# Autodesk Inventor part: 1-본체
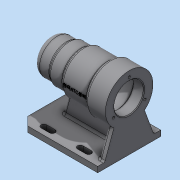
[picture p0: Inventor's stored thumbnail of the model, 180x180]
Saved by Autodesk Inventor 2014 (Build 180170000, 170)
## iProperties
Created: 2017-09
Part Number: 1-본체
Material: Generic
Document SubType Name: Modeling
Designer: user
Density: 1 g/cm^3
Appearance: Default
Author: user
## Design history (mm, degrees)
sketch "Sketch1"
  geometry: L1 (0, 0)-(25, 0); L2 (25, 0)-(25, 25); L3 (25, 25)-(0, 25); L4 (0, 25)-(0, 0); L5 (25, 0)-(45, 0); L6 (45, 0)-(45, 27); L7 (45, 27)-(25, 27); L8 (25, 27)-(25, 0); L9 (45, 0)-(84, 0); L10 (84, 0)-(84, 30); L11 (84, 30)-(45, 30); L12 (45, 30)-(45, 0); L13 (84, 0)-(112, 0); L14 (112, 0)-(112, 34); L15 (112, 34)-(84, 34); L16 (84, 34)-(84, 0)
  constraints: 32 end point, 8 parallel, 4 horizontal, 4 perpendicular
  dimensions: "d0" = 25 distance between parallel lines of L2 L4; "d1" = 45 distance between parallel lines of L6 L4; "d2" = 84 distance between parallel lines of L10 L4; "d3" = 112 distance between parallel lines of L14 L4; "d4" = 60 diameter of L11 L9; "d5" = 54 diameter of L7 L5; "d6" = 50 diameter of L3 L1; "d7" = 68 diameter of L15 L13
revolve "Revolution1" sketch "Sketch1" stored, may be unused: angle "d8" = 90 deg
workplane "Work Plane1"
sketch "Sketch2"
  geometry: L1 (0, -45)-(-112, -45); L2 (-112, -45)-(-112, 45); L3 (-112, 45)-(0, 45); L4 (0, 45)-(0, -45); L5 (-112, 34)-(-112, -34) reference; 3 further points
  constraints: 8 end point, 3 midpoint, 2 parallel, 1 coincident, 1 horizontal, 1 perpendicular
  dimensions: "d10" = 112 distance of L1.start L1.end; "d11" = 90 distance of L1.end L2.end
extrude "Extrusion1" join sketch "Sketch2" distance "d12" = 8; taper "d13" = 0 deg
sketch "Sketch3"
  geometry: L1 (0, 45)-(0, -45) reference; L2 (112, -45)-(112, 45) reference; L3 (22, 4)-(112, 4); L4 (112, 4)-(112, -4); L5 (112, -4)-(22, -4); L6 (22, -4)-(22, 4); 2 further points
  constraints: 8 end point, 2 midpoint, 2 parallel, 1 horizontal, 1 perpendicular, 1 point on line
  dimensions: "d14" = 22 distance between parallel lines of L6 L1; "d15" = 8 distance of L5.end L3.start
extrude "Extrusion2" join sketch "Sketch3" stored distance "d16" = 8; taper "d17" = 0 deg
feature "FaceDraft1" dims angle "d18" = 15 deg
sketch "Sketch4"
  geometry: L1 (90, 0)-(90, 8) reference; L2 (49, 8)-(90, 8) reference; L3 (41, 8)-(41, 36.236) reference; L4 (0, 8)-(41, 8) reference; L5 (0, 0)-(0, 8) reference; L6 (10, 8)-(23.1, 43.992); L7 (80, 8)-(66.9, 43.992); L8 (49, 8)-(49, 36.236) reference; A1 r 34 centre (45, 70) between (49, 36.236) and (41, 36.236) reference
  constraints: 4 end point, 2 point on circle, 2 point on line
  dimensions: "d19" = 110 deg angle of L7 L2; "d20" = 110 deg angle of L4 L6; "d21" = 10 distance from line of L6.start L5; "d22" = 10 distance from line of L7.start L1
extrude "Extrusion5" join sketch "Sketch4" distance "d27" = 8; taper "d28" = 0 deg
chamfer "Chamfer1" distance "d29" = 12; stored, may be unused: second distance "d30" = 2, angle "d31" = 45 deg
sketch "Sketch5"
  geometry: L1 (112, -45)-(112, -35) reference; L2 (112, 45)-(12, 45) reference; L3 (76, -34)-(88, -34); L4 (76, -38)-(88, -38); L5 (88, -30)-(76, -30); L6 (24, -34)-(36, -34); L7 (36, -30)-(24, -30); L8 (24, -38)-(36, -38); L9 (76, 30)-(88, 30); L10 (76, 34)-(88, 34); L11 (88, 38)-(76, 38); L12 (24, 34)-(36, 34); L13 (24, 30)-(36, 30); L14 (36, 38)-(24, 38); A1 r 4 centre (76, -34) between (76, -30) and (76, -38); A2 r 4 centre (88, -34) between (88, -38) and (88, -30); A3 r 4 centre (36, -34) between (36, -38) and (36, -30); A4 r 4 centre (24, -34) between (24, -30) and (24, -38); A5 r 4 centre (76, 34) between (76, 38) and (76, 30); A6 r 4 centre (88, 34) between (88, 30) and (88, 38); A7 r 4 centre (36, 34) between (36, 30) and (36, 38); A8 r 4 centre (24, 34) between (24, 38) and (24, 30); 5 further points
  constraints: 32 end point, 16 point on circle, 16 tangent, 8 centre point, 5 horizontal alignment, 5 parallel, 4 midpoint, 2 vertical alignment
  dimensions: "d32" = 12 distance of L3.start L3.end; "d33" = 8 distance between parallel lines of L4 L5; "d34" = 12 distance of L6.start L6.end; "d35" = 8 distance between parallel lines of L8 L7; "d36" = 12 distance of L10.start L10.end; "d37" = 8 distance between parallel lines of L9 L11; "d38" = 12 distance of L12.start L12.end; "d39" = 8 distance between parallel lines of L13 L14; "d40" = 34 vertical distance of L12.start point (0, 0); "d41" = 34 vertical distance of L6.start point (0, 0); "d42" = 40 distance of L3.start L6.end; "d43" = 24 distance from line of L3.end L1
extrude "Extrusion6" cut sketch "Sketch5" stored distance "d44" = 8; taper "d45" = 0 deg
sketch "Sketch6"
  geometry: L1 (6, 10.5)-(9, 10.5); L2 (9, 10.5)-(9, 0); L3 (9, 0)-(6, 0); L4 (6, 0)-(6, 10.5); L5 (9, 0)-(13, 0); L6 (13, 0)-(13, 16); L7 (13, 16)-(9, 16); L8 (9, 16)-(9, 0); L9 (13, 0)-(31, 0); L10 (31, 0)-(31, 17.5); L11 (31, 17.5)-(13, 17.5); L12 (13, 17.5)-(13, 0); L13 (31, 0)-(43, 0); L14 (43, 0)-(43, 21); L15 (43, 21)-(31, 21); L16 (31, 21)-(31, 0); L17 (43, 0)-(97, 0); L18 (97, 0)-(97, 24); L19 (97, 24)-(43, 24); L20 (43, 24)-(43, 0); L21 (97, 0)-(112, 0); L22 (112, 0)-(112, 21); L23 (112, 21)-(97, 21); L24 (97, 21)-(97, 0); L25 (112, -26.008)-(112, 34) reference; 1 further point
  constraints: 48 end point, 12 parallel, 7 horizontal alignment, 6 horizontal, 6 perpendicular, 1 point on line
  dimensions: "d46" = 18 distance between parallel lines of L10 L12; "d47" = 12 distance between parallel lines of L14 L10; "d48" = 54 distance between parallel lines of L18 L20; "d49" = 15 distance between parallel lines of L22 L18; "d50" = 4 distance between parallel lines of L12 L8; "d51" = 3 distance between parallel lines of L8 L4; "d52" = 42 diameter of L23 L21; "d53" = 48 diameter of L19 L17; "d54" = 42 diameter of L15 L13; "d55" = 35 diameter of L11 L9; "d56" = 32 diameter of L7 L5; "d57" = 21 diameter of L1 L3; "d59" = 13 distance from line of L25.end L23
revolve "Revolution2" sketch "Sketch6" stored, may be unused: angle "d58" = 90 deg
fillet "Fillet1" dims "d60" = 9
fillet "Fillet2" dims "d62" = 0.3
fillet "Fillet3" dims "d63" = 3
chamfer "Chamfer2" distance "d64" = 1; stored, may be unused: second distance "d65" = 2, angle "d66" = 45 deg
sketch "Sketch7" dims "d67" = 52
  geometry: C1 r 22 at (45, 70) reference; 2 further points
  constraints: 1 coincident, 1 vertical alignment, 2 other
hole "Hole1" sketch "Sketch7" at (45, 96) diameter "d68" = 3.242; stored, may be unused: countersink angle "d72" = 90 deg, drill point angle "d74" = 118 deg; dims "d69" = 8, "d70" = 4, "d71" = 2, "d73" = 11
pattern_circular "Circular Pattern1" dims angle "d76" = 360 deg
fillet "Fillet4" dims "d78" = 3
fillet "Fillet5" dims "d79" = 3
fillet "Fillet6" dims "d80" = 3
workplane "Work Plane2"
sketch "Sketch8"
  geometry: L1 (45, 70)-(15, 70); A1 r 30 centre (45, 70) between (49, 40.268) and (41, 40.268) reference; 2 further points
  constraints: 2 end point, 1 coincident, 1 horizontal, 1 point on circle
workplane "Work Plane4"
sketch "Sketch10"
  geometry: L1 (-16, -29.732)-(-16, -29.732) reference; L2 (-16, -29.732)-(17, -29.732) reference; L3 (17, -29.732)-(17, -29.732) reference; L4 (17, -29.732)-(-16, -29.732) reference; 3 further points
  constraints: 1 coincident, 1 other
emboss "Emboss1" sketch "Sketch10" dims "d0" = 25, "d1" = 45, "d2" = 84, "d3" = 112, "d4" = 60, "d5" = 54, "d6" = 50, "d7" = 68, "d82" = 0.5, "d83" = 0
body "Solid1"
node "Projected Loop1"
other parameters: "d81" = -48
